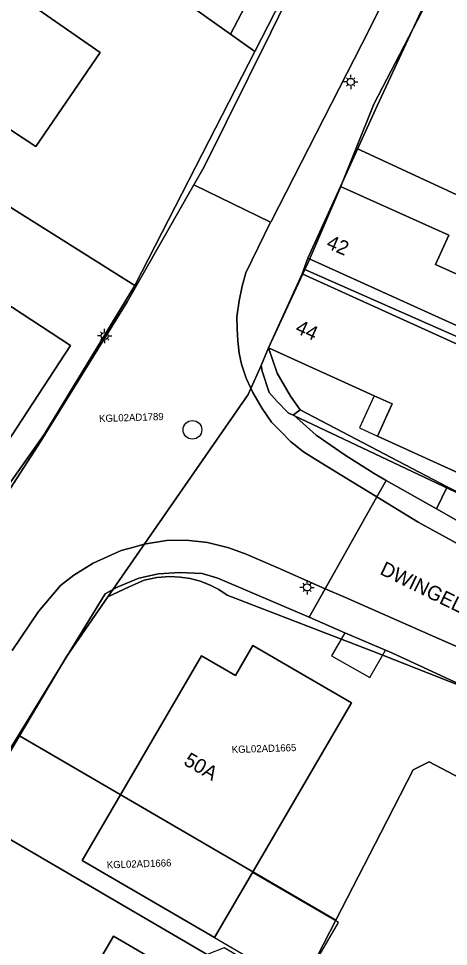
# Model space of a CAD drawing. Extents: x 124901 to 125496, y 515369 to 515789.
# Drawn here: x 125097.3 to 125127.2, y 515624.4 to 515689 of the extents above; entities that cross this region are included whole.
import ezdxf

# ---------------------------------------------------------------- set-up
doc = ezdxf.new("R2010")
doc.units = 0
for name, color, linetype in [('Gebouw', 7, 'Continuous'), ('Inrit', 7, 'Continuous'), ('Lichtmast', 7, 'Continuous'), ('Luifel', 7, 'Continuous'), ('Onbegroeid terrein', 7, 'Continuous'), ('Overige bouwwerk', 7, 'Continuous'), ('Perceelnummers', 7, 'Continuous'), ('Perceelsgrenzen', 7, 'Continuous'), ('Putten', 7, 'Continuous'), ('Teksten', 7, 'Continuous'), ('Vegetatie', 7, 'Continuous'), ('Voetpad', 7, 'Continuous'), ('Wegen drempel verkeerseiland', 7, 'Continuous'), ('Wegen lokale weg', 7, 'Continuous')]:
    doc.layers.add(name, color=color, linetype=linetype)

msp = doc.modelspace()

# ---------------------------------------------------------------- linework, layer by layer
at = {"layer": 'Gebouw'}
for points in [[(125096.737, 515681.215), (125098.51, 515680.037), (125102.984, 515686.589), (125095.901, 515691.504), (125099.16, 515696.274), (125090.537, 515702.263), (125086.904, 515697.005), (125089.809, 515695.053), (125085.411, 515688.655), (125090.712, 515684.992), (125089.312, 515682.989), (125095.208, 515678.973)], [(125129.724, 515666.712), (125131.063, 515669.674), (125130.17, 515670.078), (125126.317, 515671.819), (125127.242, 515673.866), (125119.699, 515677.263), (125117.44, 515672.263)], [(125092.378, 515653.149), (125100.905, 515666.187), (125086.687, 515675.486), (125080.814, 515666.506), (125081.38, 515666.136), (125078.726, 515662.078)], [(125117.039, 515671.19), (125114.695, 515666.031), (125122.045, 515662.693), (125123.292, 515662.126), (125122.276, 515659.888), (125130.79, 515656.015), (125131.591, 515657.78), (125132.032, 515658.748), (125129.753, 515659.783), (125130.532, 515661.499), (125129.613, 515661.916), (125131.304, 515665.773), (125129.505, 515666.59), (125129.105, 515665.71)], [(125112.392, 515643.214), (125110.028, 515644.592), (125101.727, 515630.345), (125110.943, 515624.975), (125113.588, 515629.514), (125120.464, 515641.317), (125113.612, 515645.309)], [(125110.882, 515621.141), (125110.823, 515621.04), (125103.905, 515625.07), (125098.497, 515615.788), (125115.151, 515606.085), (125112.602, 515601.71), (125114.707, 515600.484), (125118.201, 515598.448), (125126.217, 515612.207), (125122.149, 515614.577), (125111.596, 515620.725)]]:
    msp.add_lwpolyline(points, close=True, dxfattribs=at)
at = {"layer": 'Inrit'}
msp.add_lwpolyline([(125126.389, 515654.81), (125128.049, 515653.866), (125128.874, 515655.495), (125127.143, 515656.345)], close=True, dxfattribs=at)
at = {"layer": 'Lichtmast'}
for p, q in [((125120.206, 515684.748), (125120.136, 515684.819)), ((125120.418, 515684.836), (125120.418, 515685.036)), ((125120.63, 515684.748), (125120.701, 515684.82)), ((125120.118, 515684.537), (125119.918, 515684.536)), ((125120.206, 515684.324), (125120.134, 515684.253)), ((125120.418, 515684.236), (125120.418, 515684.036)), ((125120.63, 515684.324), (125120.7, 515684.253)), ((125120.718, 515684.536), (125120.918, 515684.536)), ((125103.292, 515667.153), (125103.292, 515667.353)), ((125102.992, 515666.854), (125102.792, 515666.853)), ((125103.08, 515666.641), (125103.008, 515666.57)), ((125103.08, 515667.065), (125103.01, 515667.136)), ((125103.504, 515667.065), (125103.575, 515667.137)), ((125103.504, 515666.641), (125103.574, 515666.57)), ((125103.592, 515666.853), (125103.792, 515666.853)), ((125103.292, 515666.553), (125103.292, 515666.353)), ((125117.382, 515649.652), (125117.382, 515649.852)), ((125117.082, 515649.353), (125116.882, 515649.352)), ((125117.17, 515649.14), (125117.098, 515649.069)), ((125117.17, 515649.564), (125117.1, 515649.635)), ((125117.594, 515649.564), (125117.665, 515649.636)), ((125117.594, 515649.14), (125117.664, 515649.069)), ((125117.682, 515649.352), (125117.882, 515649.352)), ((125117.382, 515649.052), (125117.382, 515648.852))]:
    msp.add_line(p, q, dxfattribs=at)
for centre in [(125120.418, 515684.536), (125103.292, 515666.853), (125117.382, 515649.352)]:
    msp.add_circle(centre, 0.25, dxfattribs=at)
at = {"layer": 'Luifel'}
msp.add_lwpolyline([(125122.276, 515659.888), (125123.292, 515662.126), (125122.045, 515662.693), (125121.028, 515660.455)], close=True, dxfattribs=at)
at = {"layer": 'Onbegroeid terrein'}
for points in [[(125132.057, 515703.978), (125122.249, 515682.88), (125119.699, 515677.263), (125127.242, 515673.866), (125126.317, 515671.819), (125130.17, 515670.078)], [(125073.228, 515622.617), (125075.311, 515626.278), (125079.729, 515634.043), (125086.43, 515644.565), (125086.531, 515644.661), (125086.621, 515644.747), (125089.281, 515645.41), (125089.462, 515645.498), (125089.591, 515645.587), (125089.696, 515645.675), (125091.656, 515648.529), (125092.693, 515650.039), (125098.859, 515659.525), (125104.868, 515669.219), (125109.5, 515677.38), (125110.211, 515678.634), (125114.857, 515687.989), (125119.179, 515696.811)], [(125129.724, 515666.712), (125117.44, 515672.263), (125117.039, 515671.19), (125129.105, 515665.71)], [(125130.79, 515656.015), (125122.276, 515659.888), (125123.292, 515662.126), (125122.045, 515662.693), (125114.695, 515666.031), (125115.297, 515664.275), (125116.22, 515662.665), (125116.893, 515661.713), (125127.143, 515656.345), (125128.874, 515655.495)], [(125149.357, 515623.506), (125153.011, 515630.042), (125151.072, 515631.046), (125151.126, 515631.154), (125144.881, 515634.349), (125137.288, 515638.226), (125135.859, 515638.966), (125123.279, 515644.801), (125122.838, 515644.99), (125120.016, 515646.2), (125117.521, 515647.27), (125111.164, 515649.996), (125110.071, 515650.329), (125108.495, 515650.388), (125107.048, 515650.295), (125105.667, 515649.993), (125104.17, 515649.357), (125103.319, 515648.9), (125091.073, 515628.943), (125090.11, 515627.331), (125083.94, 515617.184)], [(125098.497, 515615.788), (125103.905, 515625.07), (125110.823, 515621.04)]]:
    msp.add_lwpolyline(points, dxfattribs=at)
for points in [[(125098.51, 515680.037), (125096.737, 515681.215), (125095.208, 515678.973), (125089.312, 515682.989), (125090.712, 515684.992), (125085.411, 515688.655), (125089.809, 515695.053), (125086.904, 515697.005), (125090.537, 515702.263), (125099.16, 515696.274), (125095.901, 515691.504), (125102.984, 515686.589)], [(125100.905, 515666.187), (125092.378, 515653.149), (125078.726, 515662.078), (125081.38, 515666.136), (125080.814, 515666.506), (125086.687, 515675.486)], [(125110.028, 515644.592), (125112.392, 515643.214), (125113.612, 515645.309), (125120.464, 515641.317), (125113.588, 515629.514), (125110.943, 515624.975), (125101.727, 515630.345)]]:
    msp.add_lwpolyline(points, close=True, dxfattribs=at)
at = {"layer": 'Overige bouwwerk'}
for points in [[(125120.016, 515646.2), (125119.092, 515644.583), (125121.74, 515643.07), (125122.838, 515644.99)], [(125116.931, 515621.486), (125119.575, 515626.025), (125113.588, 515629.514), (125110.943, 515624.975)]]:
    msp.add_lwpolyline(points, close=True, dxfattribs=at)
at = {"layer": 'Perceelsgrenzen'}
for points in [[(125081.473, 515685.414), (125074.421, 515689.851), (125062.069, 515697.48), (125063.132, 515697.834), (125063.426, 515697.932), (125086.431, 515705.598), (125108.544, 515690.373), (125112.041, 515687.866), (125113.735, 515686.647), (125112.864, 515684.95), (125105.41, 515670.408), (125105.386, 515670.369)], [(125112.041, 515687.866), (125108.544, 515690.373), (125103.66, 515694.375), (125098.704, 515699.274), (125100.225, 515703.457), (125100.976, 515704.144), (125115.337, 515694.17)], [(125166.926, 515659.032), (125140.083, 515670.591), (125140.316, 515671.134), (125132.566, 515674.471), (125120.79, 515679.928), (125122.019, 515683), (125126.585, 515691.761), (125128.453, 515695.933), (125147.554, 515685.104), (125174.097, 515673.025), (125174.35, 515672.91), (125167.115, 515658.839)], [(125112.041, 515687.866), (125115.337, 515694.17), (125116.999, 515693.015), (125113.735, 515686.647)], [(125087.116, 515643.882), (125086.956, 515643.676), (125086.773, 515643.441), (125077.371, 515654.277), (125066.493, 515666.995), (125057.754, 515677.336), (125060.223, 515679.19), (125074.421, 515689.851), (125081.473, 515685.414), (125105.386, 515670.369), (125099.087, 515659.997), (125093.45, 515652.027)], [(125164.083, 515652.43), (125136.774, 515664.118), (125129.222, 515666.532), (125129.098, 515666.243), (125117.233, 515671.492), (125117.383, 515671.815), (125119.66, 515677.103), (125120.79, 515679.928), (125132.566, 515674.471), (125140.316, 515671.134), (125140.083, 515670.591), (125166.926, 515659.032), (125164.142, 515652.565)], [(125114.189, 515664.798), (125114.695, 515666.031), (125117.233, 515671.492), (125129.098, 515666.243), (125129.222, 515666.532), (125136.774, 515664.118), (125164.083, 515652.43), (125164.476, 515652.261), (125158.612, 515640.872), (125150.14, 515644.966), (125149.938, 515644.848), (125144.877, 515647.428), (125145.022, 515647.748), (125132.438, 515653.743), (125116.073, 515661.512), (125115.299, 515662.299), (125114.744, 515662.908), (125114.254, 515664.4)], [(125129.32, 515635.402), (125125.868, 515637.219), (125124.759, 515636.662), (125122.509, 515632.26), (125119.387, 515626.196), (125097.361, 515639.025), (125100.606, 515644.506), (125103.503, 515648.705), (125104.988, 515649.402), (125106.037, 515649.863), (125106.926, 515650.045), (125107.832, 515650.107), (125108.542, 515650.071), (125109.244, 515649.961), (125109.931, 515649.779), (125110.595, 515649.526), (125111.229, 515649.205), (125111.826, 515648.819), (125121.926, 515644.905), (125130.366, 515641.588), (125132.494, 515640.518), (125131.779, 515640.164)], [(125094.787, 515635.584), (125096.223, 515637.971), (125096.611, 515637.757), (125097.361, 515639.025), (125119.387, 515626.196), (125116.825, 515621.224), (125111.621, 515624.256), (125110.434, 515623.79), (125093.595, 515633.603)]]:
    msp.add_lwpolyline(points, close=True, dxfattribs=at)
for points in [[(125072.681, 515622.173), (125080.294, 515636.377), (125080.977, 515635.987), (125085.951, 515642.383), (125086.773, 515643.441), (125086.956, 515643.676), (125087.116, 515643.882), (125093.45, 515652.027), (125099.087, 515659.997), (125105.386, 515670.369), (125105.41, 515670.408), (125112.864, 515684.95), (125113.735, 515686.647), (125116.999, 515693.015)], [(125126.585, 515691.761), (125122.019, 515683), (125120.79, 515679.928), (125119.66, 515677.103), (125117.383, 515671.815), (125117.233, 515671.492), (125114.695, 515666.031), (125114.189, 515664.798), (125113.279, 515662.773), (125103.503, 515648.705), (125100.606, 515644.506), (125097.361, 515639.025), (125096.611, 515637.757), (125096.223, 515637.971), (125094.787, 515635.584), (125093.595, 515633.603), (125089.274, 515626.42), (125084.2, 515617.939)], [(125130.366, 515641.588), (125121.926, 515644.905), (125111.826, 515648.819), (125111.229, 515649.205), (125110.595, 515649.526), (125109.931, 515649.779), (125109.244, 515649.961), (125108.542, 515650.071), (125107.832, 515650.107), (125106.926, 515650.045), (125106.037, 515649.863), (125104.988, 515649.402), (125103.503, 515648.705), (125113.279, 515662.773), (125114.189, 515664.798), (125114.254, 515664.4), (125114.744, 515662.908), (125115.299, 515662.299), (125116.073, 515661.512), (125132.438, 515653.743)], [(125116.825, 515621.224), (125119.387, 515626.196), (125122.509, 515632.26), (125124.759, 515636.662), (125125.868, 515637.219), (125129.32, 515635.402), (125131.779, 515640.164), (125132.494, 515640.518), (125136.628, 515638.439), (125131.339, 515627.899), (125126.878, 515619.009)], [(125084.2, 515617.939), (125089.274, 515626.42), (125093.595, 515633.603), (125110.434, 515623.79)]]:
    msp.add_lwpolyline(points, dxfattribs=at)
at = {"layer": 'Putten'}
msp.add_circle((125109.4, 515660.32), 0.65, dxfattribs=at)
at = {"layer": 'Vegetatie'}
msp.add_lwpolyline([(125122.885, 515656.802), (125126.389, 515654.81), (125127.143, 515656.345), (125116.893, 515661.713), (125116.444, 515661.354), (125118.025, 515659.939), (125120.038, 515658.552), (125122.049, 515657.277)], close=True, dxfattribs=at)
at = {"layer": 'Voetpad'}
for points in [[(125126.75, 515698.247), (125121.195, 515687.161), (125114.87, 515674.83), (125114.841, 515674.77), (125113.118, 515671.245), (125112.86, 515670.326), (125112.646, 515669.301), (125112.496, 515668.188), (125112.522, 515667.35), (125112.568, 515666.508), (125112.663, 515665.661), (125112.828, 515664.894), (125113.152, 515663.913), (125113.441, 515663.271), (125113.604, 515662.909), (125114.253, 515661.795), (125114.912, 515660.852), (125115.597, 515660.167), (125116.231, 515659.499), (125117.123, 515658.781), (125118.058, 515658.203), (125120.516, 515656.705), (125122.239, 515655.654), (125122.885, 515656.802), (125122.049, 515657.277), (125120.038, 515658.552), (125118.025, 515659.939), (125116.444, 515661.354), (125116.893, 515661.713), (125116.22, 515662.665), (125115.297, 515664.275), (125114.695, 515666.031), (125117.039, 515671.19), (125117.44, 515672.263), (125119.699, 515677.263), (125122.249, 515682.88), (125132.057, 515703.978)], [(125091.073, 515628.943), (125103.319, 515648.9), (125104.17, 515649.357), (125105.667, 515649.993), (125107.048, 515650.295), (125108.495, 515650.388), (125110.071, 515650.329), (125111.164, 515649.996), (125117.521, 515647.27), (125118.642, 515649.262), (125115.344, 515650.707), (125113.139, 515651.656), (125111.924, 515652.116), (125110.457, 515652.48), (125108.966, 515652.646), (125107.588, 515652.617), (125106.052, 515652.36), (125105.32, 515652.162), (125104.436, 515651.922), (125102.499, 515651.029), (125101.144, 515650.196), (125100.211, 515649.477), (125098.676, 515647.685), (125096.857, 515644.957)]]:
    msp.add_lwpolyline(points, dxfattribs=at)
for points in [[(125154.759, 515638.463), (125155.301, 515639.553), (125150.844, 515641.866), (125145.773, 515644.497), (125139.473, 515647.766), (125130.875, 515652.26), (125129.872, 515652.83), (125128.049, 515653.866), (125126.389, 515654.81), (125122.885, 515656.802), (125122.239, 515655.654), (125125.108, 515653.904), (125134.135, 515648.948)], [(125135.859, 515638.966), (125137.288, 515638.226), (125144.881, 515634.349), (125151.126, 515631.154), (125152.094, 515633.102), (125138.391, 515640.193), (125132.228, 515643.284), (125126.206, 515645.933), (125120.045, 515648.647), (125118.642, 515649.262), (125117.521, 515647.27), (125120.016, 515646.2), (125122.838, 515644.99), (125123.279, 515644.801)]]:
    msp.add_lwpolyline(points, close=True, dxfattribs=at)
at = {"layer": 'Wegen drempel verkeerseiland'}
msp.add_lwpolyline([(125096.857, 515644.957), (125098.676, 515647.685), (125100.211, 515649.477), (125101.144, 515650.196), (125102.499, 515651.029), (125104.436, 515651.922), (125105.32, 515652.162), (125106.052, 515652.36), (125107.588, 515652.617), (125108.966, 515652.646), (125110.457, 515652.48), (125111.924, 515652.116), (125113.139, 515651.656), (125115.344, 515650.707), (125118.642, 515649.262), (125122.239, 515655.654), (125120.516, 515656.705), (125118.058, 515658.203), (125117.123, 515658.781), (125116.231, 515659.499), (125115.597, 515660.167), (125114.912, 515660.852), (125114.253, 515661.795), (125113.604, 515662.909), (125113.441, 515663.271), (125113.152, 515663.913), (125112.828, 515664.894), (125112.663, 515665.661), (125112.568, 515666.508), (125112.522, 515667.35), (125112.496, 515668.188), (125112.646, 515669.301), (125112.86, 515670.326), (125113.118, 515671.245), (125114.841, 515674.77), (125109.5, 515677.38), (125104.868, 515669.219), (125098.859, 515659.525), (125092.693, 515650.039)], dxfattribs=at)
at = {"layer": 'Wegen lokale weg'}
msp.add_lwpolyline([(125152.686, 515766.719), (125152.224, 515766.949), (125146.998, 515755.898), (125145.256, 515752.258), (125144.609, 515750.907), (125135.973, 515731.393), (125129.13, 515717.194), (125122.168, 515702.811), (125119.179, 515696.811), (125114.857, 515687.989), (125110.211, 515678.634), (125109.5, 515677.38), (125114.841, 515674.77), (125114.87, 515674.83), (125121.195, 515687.161), (125126.75, 515698.247), (125131.829, 515708.15), (125137.289, 515719.132), (125147.289, 515740.344), (125158.271, 515763.978), (125168.476, 515784.043)], dxfattribs=at)
msp.add_lwpolyline([(125118.642, 515649.262), (125120.045, 515648.647), (125126.206, 515645.933), (125132.228, 515643.284), (125138.391, 515640.193), (125152.094, 515633.102), (125154.759, 515638.463), (125134.135, 515648.948), (125125.108, 515653.904), (125122.239, 515655.654)], close=True, dxfattribs=at)

# ---------------------------------------------------------------- texts
at = {"layer": 'Perceelnummers'}
for s, rotation, p in [('KGL02AD1789', 1.82925, (125102.91, 515660.86)), ('KGL02AD1665', 1.82936, (125112.143, 515637.817)), ('KGL02AD1666', 1.82925, (125103.446, 515629.79))]:
    msp.add_text(s, height=0.5, rotation=rotation, dxfattribs=at).set_placement(p)
at = {"layer": 'Teksten'}
for s, rotation, p in [('42', 336.7, (125118.648, 515673.01)), ('44', 335.6, (125116.491, 515667.114)), ('DWINGEL', 333.9, (125122.378, 515650.305)), ('50A', 329.8, (125108.723, 515637.055))]:
    msp.add_text(s, height=1, rotation=rotation, dxfattribs=at).set_placement(p)

doc.saveas('drawing.dxf')
